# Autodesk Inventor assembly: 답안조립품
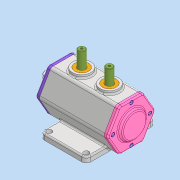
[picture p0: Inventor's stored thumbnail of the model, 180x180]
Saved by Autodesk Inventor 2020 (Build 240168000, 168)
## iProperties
Created: 2021-06
Part Number: 답안조립품
Document SubType Name: Assembly
Designer: Administrator
Author: Administrator
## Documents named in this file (11)
- C:\Users\Administrator\Desktop\710606V1021\답안조립품.iam
- C:\Users\Administrator\Desktop\710606V1021\본체.ipt
- C:\Users\Administrator\Desktop\710606V1021\편심축.ipt
- C:\Users\Administrator\Desktop\710606V1021\베어링 6302.ipt
- C:\Users\Administrator\Desktop\710606V1021\뒷커버.ipt
- C:\Users\Administrator\Desktop\710606V1021\볼트 M4.ipt
- C:\Users\Administrator\Desktop\710606V1021\베어링 6203.ipt
- C:\Users\Administrator\Desktop\710606V1021\부시.ipt
- C:\Users\Administrator\Desktop\710606V1021\슬라이더.ipt
- C:\Users\Administrator\Desktop\710606V1021\앞커버.ipt
- C:\Users\Administrator\Desktop\710606V1021\오일실.ipt
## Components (10 placed, 3 different names)
1. 7-베어링 6203:1
2. 8-오일실:1
3. 9-M4-소켓머리:1
4. 9-M4-소켓머리:2
5. 9-M4-소켓머리:3
6. 9-M4-소켓머리:4
7. 9-M4-소켓머리:5
8. 9-M4-소켓머리:6
9. 9-M4-소켓머리:7
10. 9-M4-소켓머리:8
